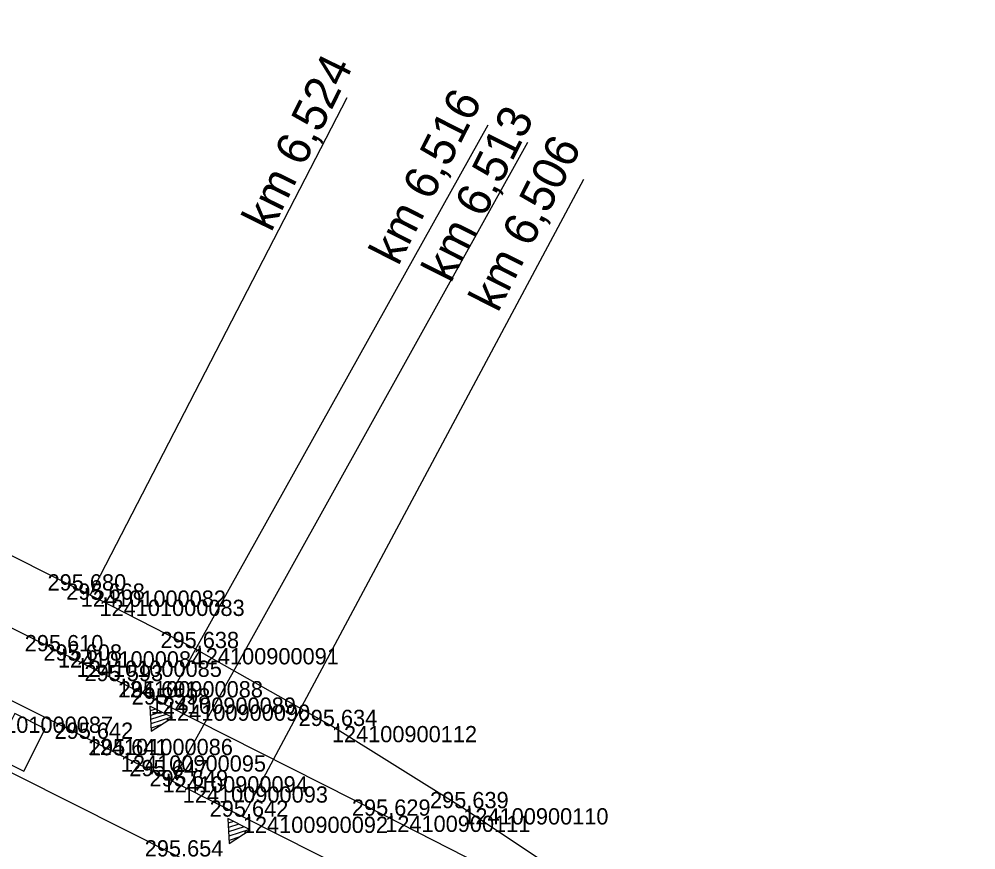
# Model space of a CAD drawing. Extents: x -616949 to -607976, y -1164436 to -1159224.
# Drawn here: x -612906.9 to -612836.3, y -1161703.8 to -1161642.5 of the extents above; entities that cross this region are included whole.
import ezdxf

# ---------------------------------------------------------------- set-up
doc = ezdxf.new("R2010")
doc.units = 0
for name, color, linetype in [('Vrstva 1', 7, 'Continuous'), ('Vrstva 3', 7, 'Continuous'), ('Vrstva 4', 7, 'Continuous'), ('Vrstva 60', 7, 'Continuous'), ('Vrstva 61', 7, 'Continuous'), ('Vrstva 7', 7, 'Continuous')]:
    doc.layers.add(name, color=color, linetype=linetype)

msp = doc.modelspace()

# ---------------------------------------------------------------- linework, layer by layer
at = {"layer": 'Vrstva 1'}
for points in [[(-612836.296, -1161723.704), (-612837.638, -1161723.012), (-612850.997, -1161716.121), (-612864.797, -1161706.958), (-612874.107, -1161700.736), (-612883.802, -1161694.669), (-612893.994, -1161688.921), (-612900.943, -1161685.35), (-612902.323, -1161684.67), (-612923.958, -1161673.819), (-612946.699, -1161662.429), (-612968.712, -1161651.4), (-612992.183, -1161639.631), (-613014.55, -1161628.424), (-613038.927, -1161616.218), (-613057.435, -1161606.931), (-613076.92, -1161597.16), (-613100.259, -1161585.472), (-613122.657, -1161574.252), (-613146.782, -1161562.201), (-613166.98, -1161552.106), (-613189.634, -1161540.788)], [(-612836.296, -1161723.704), (-612837.638, -1161723.012), (-612850.997, -1161716.121), (-612865.701, -1161708.536), (-612879.868, -1161701.287), (-612896.114, -1161693.083), (-612897.161, -1161692.563), (-612899.596, -1161691.357), (-612902.625, -1161689.845), (-612904.006, -1161689.155), (-612926.343, -1161677.972), (-612949.005, -1161666.636), (-612970.853, -1161655.686), (-612994.196, -1161644.017), (-613016.803, -1161632.705), (-613041.115, -1161620.531), (-613059.386, -1161611.38), (-613079.385, -1161601.373), (-613102.396, -1161589.858), (-613124.84, -1161578.629), (-613149.327, -1161566.383), (-613169.01, -1161556.539), (-613191.83, -1161545.118)], [(-612838.403, -1161727.968), (-612839.523, -1161727.391), (-612849.62, -1161722.193), (-612861.867, -1161715.888), (-612876.821, -1161708.208), (-612890.369, -1161701.36), (-612894.801, -1161699.124), (-612896.288, -1161698.374), (-612899.369, -1161696.835), (-612901.81, -1161695.618), (-612928.777, -1161682.133), (-612951.306, -1161670.848), (-612973.151, -1161659.899), (-612996.391, -1161648.275), (-613019.153, -1161636.875), (-613042.978, -1161624.976), (-613061.364, -1161615.727), (-613081.954, -1161605.444), (-613104.413, -1161594.192), (-613127.642, -1161582.549), (-613152.331, -1161570.198), (-613170.826, -1161560.946), (-613193.857, -1161549.424)], [(-612838.403, -1161727.968), (-612839.523, -1161727.391), (-612849.62, -1161722.193), (-612862.617, -1161717.556), (-612874.036, -1161713.428), (-612884.823, -1161709.136), (-612890.215, -1161706.69), (-612892.638, -1161705.537), (-612895.153, -1161704.298), (-612918.738, -1161692.452), (-613021.426, -1161641.023), (-613045.295, -1161629.074), (-613063.439, -1161619.971), (-613084.102, -1161609.632), (-613106.492, -1161598.411), (-613129.982, -1161586.613), (-613154.545, -1161574.228)]]:
    msp.add_lwpolyline(points, dxfattribs=at)
at = {"layer": 'Vrstva 3'}
for p, q in [((-612901.633, -1161685.01), (-612882.678, -1161648.283)), ((-612896.114, -1161693.083), (-612872.268, -1161650.307)), ((-612895.545, -1161698.749), (-612869.339, -1161651.586)), ((-612890.369, -1161701.36), (-612865.226, -1161654.305)), ((-612900.943, -1161685.35), (-612902.323, -1161684.67)), ((-612902.625, -1161689.845), (-612904.006, -1161689.155)), ((-612896.792, -1161693.429), (-612897.197, -1161693.56)), ((-612896.402, -1161693.628), (-612897.183, -1161693.882)), ((-612896.019, -1161693.822), (-612897.168, -1161694.201)), ((-612895.628, -1161694.021), (-612897.146, -1161694.516)), ((-612896.412, -1161694.595), (-612897.126, -1161694.834)), ((-612894.801, -1161699.124), (-612896.288, -1161698.374)), ((-612891.047, -1161701.708), (-612891.451, -1161701.84)), ((-612890.656, -1161701.905), (-612891.436, -1161702.162)), ((-612890.273, -1161702.099), (-612891.42, -1161702.48)), ((-612889.881, -1161702.297), (-612891.398, -1161702.795)), ((-612890.664, -1161702.873), (-612891.378, -1161703.114))]:
    msp.add_line(p, q, dxfattribs=at)
for points in [[(-612897.119, -1161695.06), (-612895.567, -1161694.052), (-612897.219, -1161693.213)], [(-612891.37, -1161703.339), (-612889.82, -1161702.327), (-612891.473, -1161701.492)]]:
    msp.add_lwpolyline(points, close=True, dxfattribs=at)
at = {"layer": 'Vrstva 4'}
for p, q in [((-612897.161, -1161692.563), (-612899.596, -1161691.357)), ((-612899.369, -1161696.835), (-612901.81, -1161695.618))]:
    msp.add_line(p, q, dxfattribs=at)
at = {"layer": 'Vrstva 60'}
for p, q in [((-612902.323, -1161684.67), (-612902.323, -1161684.67)), ((-612900.943, -1161685.35), (-612900.943, -1161685.35)), ((-612893.994, -1161688.921), (-612893.994, -1161688.921)), ((-612904.006, -1161689.155), (-612904.006, -1161689.155)), ((-612902.625, -1161689.845), (-612902.625, -1161689.845)), ((-612899.596, -1161691.357), (-612899.596, -1161691.357)), ((-612897.161, -1161692.563), (-612897.161, -1161692.563)), ((-612896.114, -1161693.083), (-612896.114, -1161693.083)), ((-612883.802, -1161694.669), (-612883.802, -1161694.669)), ((-612901.81, -1161695.618), (-612901.81, -1161695.618)), ((-612899.369, -1161696.835), (-612899.369, -1161696.835)), ((-612896.288, -1161698.374), (-612896.288, -1161698.374)), ((-612894.801, -1161699.124), (-612894.801, -1161699.124)), ((-612874.107, -1161700.736), (-612874.107, -1161700.736)), ((-612890.369, -1161701.36), (-612890.369, -1161701.36)), ((-612879.868, -1161701.287), (-612879.868, -1161701.287))]:
    msp.add_line(p, q, dxfattribs=at)
at = {"layer": 'Vrstva 7'}
msp.add_lwpolyline([(-612910.65, -1161693.976), (-612907.967, -1161695.318), (-612908.749, -1161696.883), (-612906.513, -1161698.001), (-612904.948, -1161694.871), (-612907.184, -1161693.753), (-612907.967, -1161695.318)], dxfattribs=at)

# ---------------------------------------------------------------- texts
at = {"layer": 'Vrstva 3'}
for s, rotation, p in [('km 6,524', 63.76806, (-612888.281, -1161658.301)), ('km 6,516', 63.06464, (-612878.91, -1161660.79)), ('km 6,513', 63.23494, (-612875.036, -1161662.062)), ('km 6,506', 63.18513, (-612871.56, -1161664.23))]:
    msp.add_text(s, height=2.5, rotation=rotation, dxfattribs=at).set_placement(p)
at = {"layer": 'Vrstva 60'}
for s, p in [('124101000082', (-612902.323, -1161685.87)), ('124101000083', (-612900.943, -1161686.55)), ('124100900091', (-612893.994, -1161690.121)), ('124101000084', (-612904.006, -1161690.355)), ('124101000085', (-612902.625, -1161691.045)), ('124100900088', (-612899.596, -1161692.557)), ('124100900089', (-612897.161, -1161693.763)), ('124100900090', (-612896.114, -1161694.283)), ('124101000087', (-612910.65, -1161695.176)), ('124100900112', (-612883.802, -1161695.869)), ('124101000086', (-612901.81, -1161696.818)), ('124100900095', (-612899.369, -1161698.035)), ('124100900094', (-612896.288, -1161699.574)), ('124100900093', (-612894.801, -1161700.324)), ('124100900110', (-612874.107, -1161701.936)), ('124100900092', (-612890.369, -1161702.56)), ('124100900111', (-612879.868, -1161702.487))]:
    msp.add_text(s, height=1.2, dxfattribs=at).set_placement(p)
at = {"layer": 'Vrstva 61'}
for s, p in [('295.680', (-612904.774, -1161684.67)), ('295.668', (-612903.397, -1161685.35)), ('295.610', (-612906.457, -1161689.155)), ('295.638', (-612896.448, -1161688.921)), ('295.608', (-612905.079, -1161689.845)), ('295.593', (-612902.048, -1161691.357)), ('295.601', (-612899.518, -1161692.563)), ('295.598', (-612898.568, -1161693.083)), ('295.634', (-612886.253, -1161694.669)), ('295.642', (-612904.258, -1161695.618)), ('295.641', (-612901.726, -1161696.835)), ('295.647', (-612898.74, -1161698.374)), ('295.649', (-612897.255, -1161699.124)), ('295.639', (-612876.561, -1161700.736)), ('295.642', (-612892.817, -1161701.36)), ('295.629', (-612882.322, -1161701.287)), ('295.654', (-612897.604, -1161704.298))]:
    msp.add_text(s, height=1.2, dxfattribs=at).set_placement(p)

doc.saveas('drawing.dxf')
